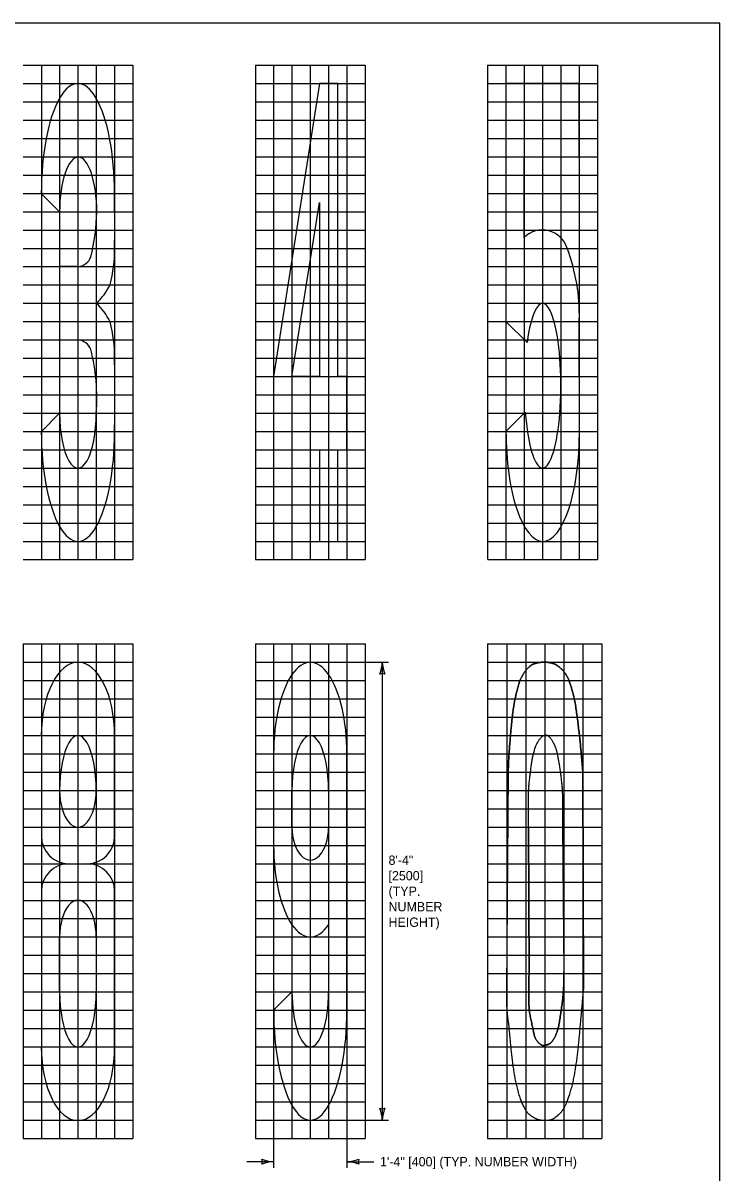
# Model space of a CAD drawing. Extents: x 49991.4 to 50021, y 49987.6 to 50011.4.
# Drawn here: x 50004.12 to 50008.61, y 50003.84 to 50011.26 of the extents above; entities that cross this region are included whole.
import ezdxf

# ---------------------------------------------------------------- set-up
doc = ezdxf.new("R2010")
doc.units = 0
for name, color, linetype in [('Level 1', 7, 'Continuous'), ('Level 2', 7, 'Continuous'), ('Level 3', 7, 'Continuous'), ('Level 9', 7, 'Continuous')]:
    doc.layers.add(name, color=color, linetype=linetype)

msp = doc.modelspace()

# ---------------------------------------------------------------- linework, layer by layer
at = {"layer": 'Level 1'}
for p, q in [((50007.7072, 50010.8724), (50007.2348, 50010.8724)), ((50007.2348, 50010.8724), (50007.2348, 50009.3367)), ((50007.7072, 50010.3999), (50007.7072, 50010.8724)), ((50007.3529, 50009.8798), (50007.3529, 50010.3999)), ((50007.3529, 50010.3999), (50007.7072, 50010.3999)), ((50004.2385, 50010.1636), (50004.3566, 50010.0456)), ((50004.7123, 50009.9274), (50004.711, 50010.1636)), ((50005.8549, 50008.9824), (50006.0321, 50010.1046)), ((50006.0321, 50010.1046), (50006.0321, 50008.9824)), ((50004.4751, 50009.6911), (50004.357, 50009.6911)), ((50004.357, 50009.6911), (50004.357, 50009.4549)), ((50004.357, 50009.4549), (50004.357, 50009.2186)), ((50007.2348, 50009.3367), (50007.3703, 50009.2012)), ((50007.7086, 50008.628), (50007.7074, 50009.3472)), ((50004.357, 50009.2186), (50004.4751, 50009.2186)), ((50005.7368, 50008.9824), (50005.7368, 50008.5099)), ((50006.0321, 50008.9824), (50005.8549, 50008.9824)), ((50006.2093, 50008.9824), (50006.1502, 50008.9824)), ((50006.2093, 50008.5099), (50006.2093, 50008.9824)), ((50004.357, 50008.7461), (50004.2389, 50008.628)), ((50007.3592, 50008.7524), (50007.2348, 50008.628)), ((50005.7368, 50008.5099), (50006.0321, 50008.5099)), ((50006.0321, 50008.5099), (50006.0321, 50007.9192)), ((50006.1502, 50007.9192), (50006.1502, 50008.5099)), ((50006.1502, 50008.5099), (50006.2093, 50008.5099)), ((50006.0321, 50007.9192), (50006.1502, 50007.9192)), ((50004.2389, 50006.6667), (50004.2389, 50006.0761)), ((50004.7114, 50006.0761), (50004.7114, 50006.6667)), ((50005.7368, 50006.5486), (50005.7368, 50005.958)), ((50006.2093, 50004.8948), (50006.2093, 50006.5486)), ((50005.855, 50006.0761), (50005.855, 50006.3123)), ((50006.0912, 50006.3123), (50006.0912, 50006.0761)), ((50004.2389, 50006.0761), (50004.2389, 50006.017)), ((50004.7114, 50006.017), (50004.7114, 50006.0761)), ((50004.2389, 50005.6626), (50004.2389, 50004.6586)), ((50004.7114, 50004.6586), (50004.7114, 50005.6626)), ((50006.0912, 50005.4465), (50006.0912, 50005.013)), ((50004.357, 50005.013), (50004.357, 50005.3673)), ((50004.5932, 50005.3673), (50004.5932, 50005.013)), ((50005.855, 50005.013), (50005.7368, 50004.8948))]:
    msp.add_line(p, q, dxfattribs=at)
msp.add_lwpolyline([(50008.6146, 50011.2628), (50000.3356, 50011.2628), (50000.3356, 50000.0624), (50008.6146, 50000.0624)], close=True, dxfattribs=at)
for points in [[(50006.1502, 50008.9824), (50006.1502, 50010.8724), (50006.0321, 50010.8724), (50005.7368, 50008.9824)], [(50007.2494, 50006.4264), (50007.2371, 50005.0264)], [(50007.7346, 50005.0284), (50007.7305, 50006.4303)], [(50007.3834, 50005.1428), (50007.3807, 50006.078)], [(50007.5988, 50006.0793), (50007.6082, 50005.1428)]]:
    msp.add_lwpolyline(points, dxfattribs=at)
for centre, radius, start, end in [((50007.4695, 50009.7605), 0.1669, 17.22202, 134.34836), ((50006.4978, 50009.38), 1.21, 358.44818, 20.8119)]:
    msp.add_arc(centre, radius, start, end, dxfattribs=at)
for centre, major_axis, ratio, start_param, end_param in [((50004.4748, 50010.1636), (0, 0.7087), 0.333309, 4.712389, 7.853982), ((50004.4766, 50010.0434), (0, -0.3544), 0.338649, 1.570796, 4.706242), ((50003.3124, 50010.0665), (0, 1.2845), 0.999928, 4.466044, 4.696062), ((49982.9544, 50010.0455), (0, 21.7597), 0.999928, 4.701532, 4.70696), ((50003.8487, 50009.7981), (0, 0.8627), 0.999928, 4.450566, 4.725288), ((50004.4655, 50009.7904), (0, 0.0998), 0.999928, 3.237525, 4.330136), ((50004.3421, 50009.7336), (0, 0.3751), 0.999928, 3.874855, 4.275301), ((50004.3421, 50009.1761), (0, 0.3751), 0.999928, 5.149477, 5.549923), ((50007.471, 50008.9233), (0, 0.5315), 0.222211, 5.501988, 7.303894), ((50003.8487, 50009.1116), (0, 0.8627), 0.999928, 4.69949, 4.974212), ((50007.471, 50008.9233), (0, 0.5315), 0.222211, 1.898175, 5.501988), ((50004.4655, 50009.1193), (0, 0.0998), 0.999928, 5.094642, 6.187253), ((50003.3124, 50008.8433), (0, 1.2845), 0.999928, 4.636675, 4.958734), ((49982.9544, 50008.8642), (0, 21.7597), 0.999928, 4.701532, 4.723246), ((50004.4751, 50008.7461), (0, 0.3544), 0.333302, 1.570796, 4.712389), ((50004.4751, 50008.628), (0, 0.7087), 0.333309, 1.570796, 4.712389), ((50007.4717, 50008.628), (0, 0.7088), 0.334262, 1.570796, 3.141593), ((50007.4717, 50008.628), (0, 0.7088), 0.334262, 3.141593, 4.712389), ((50004.4751, 50006.6667), (0, 0.4725), 0.499964, 0, 1.570796), ((50004.4751, 50006.6667), (0, 0.4725), 0.499964, 4.712389, 6.283185), ((50005.9731, 50006.5486), (0, -0.5906), 0.399971, 1.570796, 4.712389), ((50004.4751, 50006.3123), (0, 0.3544), 0.333309, 4.712389, 7.853982), ((50005.9731, 50006.3123), (0, -0.3544), 0.333309, 1.570796, 4.712389), ((50004.4751, 50006.3123), (0, 0.2363), 0.499964, 1.570796, 4.712389), ((50005.9731, 50006.0761), (0, -0.2125), 0.555853, 4.712389, 7.853982), ((50004.4161, 50006.017), (0, -0.1772), 0.999928, 4.712389, 6.283185), ((50004.5342, 50006.017), (0, -0.1772), 0.999928, 0, 1.570796), ((50005.9731, 50005.958), (0, 0.5906), 0.399971, 1.570796, 3.665191), ((50004.4161, 50005.6626), (0, -0.1772), 0.999928, 3.141593, 4.712389), ((50004.5342, 50005.6626), (0, 0.1772), 0.999928, 4.712389, 6.283185), ((50004.4751, 50005.3673), (0, 0.2363), 0.499964, 4.712389, 7.853982), ((50004.4751, 50005.013), (0, 0.3544), 0.333309, 1.570796, 4.712389), ((50005.9731, 50005.013), (0, -0.3544), 0.333309, 4.712389, 7.8539), ((50005.9731, 50004.8948), (0, 0.7087), 0.333309, 1.570796, 4.712389), ((50004.4751, 50004.6586), (0, 0.4761), 0.496158, 1.570834, 4.712389)]:
    msp.add_ellipse(centre, major_axis=major_axis, ratio=ratio, start_param=start_param, end_param=end_param, dxfattribs=at)
for points in [[(50007.7305, 50006.4303), (50007.7208, 50006.544), (50007.7095, 50006.6607), (50007.6952, 50006.7783), (50007.6787, 50006.897), (50007.6459, 50007.0126), (50007.6274, 50007.0522), (50007.6058, 50007.0838), (50007.575, 50007.1115), (50007.5462, 50007.1313), (50007.4805, 50007.1432), (50007.4158, 50007.1313), (50007.3911, 50007.1165), (50007.3665, 50007.0927), (50007.3429, 50007.0581), (50007.3223, 50007.0176), (50007.2905, 50006.899), (50007.2741, 50006.7803), (50007.2628, 50006.6587), (50007.2494, 50006.4827), (50007.2494, 50006.4264)], [(50007.3807, 50006.078), (50007.3793, 50006.1978), (50007.3793, 50006.3151), (50007.3927, 50006.4336), (50007.4074, 50006.5443), (50007.4436, 50006.641), (50007.4971, 50006.6835), (50007.5466, 50006.6139), (50007.5667, 50006.5482), (50007.5841, 50006.4374), (50007.5988, 50006.3163), (50007.5988, 50006.1953), (50007.5988, 50006.0793)], [(50007.6082, 50005.1428), (50007.6082, 50005.0243), (50007.5921, 50004.902), (50007.5747, 50004.786), (50007.5546, 50004.7281), (50007.5239, 50004.6791), (50007.4824, 50004.6662), (50007.465, 50004.6662), (50007.4235, 50004.7049), (50007.4048, 50004.7886), (50007.382, 50004.902), (50007.382, 50005.0205), (50007.3834, 50005.1428)], [(50007.2371, 50005.0264), (50007.2371, 50004.9048), (50007.2535, 50004.7872), (50007.2638, 50004.6665), (50007.2761, 50004.5519), (50007.2956, 50004.4302), (50007.3275, 50004.3136), (50007.3644, 50004.2424), (50007.3932, 50004.2147), (50007.4446, 50004.1851), (50007.5226, 50004.1851), (50007.5514, 50004.2019), (50007.5863, 50004.2315), (50007.6109, 50004.2651), (50007.6346, 50004.3146), (50007.6685, 50004.4302), (50007.689, 50004.5499), (50007.7034, 50004.6685), (50007.7136, 50004.7862), (50007.7249, 50004.9068), (50007.7346, 50005.0284)]]:
    msp.add_open_spline(points, degree=2, dxfattribs=at)
at = {"layer": 'Level 3'}
for p, q in [((50006.0731, 50007.1392), (50006.4774, 50007.1392)), ((50006.4374, 50007.1392), (50006.4374, 50004.1861)), ((50005.7368, 50004.6586), (50005.7368, 50003.8779)), ((50006.2093, 50004.6586), (50006.2093, 50003.8779)), ((50006.0731, 50004.1861), (50006.1693, 50004.1861)), ((50006.2493, 50004.1861), (50006.4774, 50004.1861)), ((50005.7368, 50003.9179), (50005.5634, 50003.9179)), ((50006.2093, 50003.9179), (50006.3827, 50003.9179))]:
    msp.add_line(p, q, dxfattribs=at)
for centre, radius, start, end in [((50006.2153, 50007.1484), 0.2223, 337.45601, 357.63952), ((50006.6701, 50007.1507), 0.233, 182.82731, 202.07716), ((50006.4374, 50007.011), 0.0548, 72.13882, 107.86118), ((50006.4374, 50004.3143), 0.0548, 252.13882, 287.86118), ((50006.2047, 50004.1746), 0.233, 2.82731, 22.07716), ((50006.6596, 50004.1769), 0.2223, 157.45601, 177.63952), ((50005.746, 50004.1401), 0.2223, 247.45601, 267.63952), ((50005.6086, 50003.9179), 0.0548, 342.13882, 17.86118), ((50005.7483, 50003.6852), 0.233, 92.82731, 112.07716), ((50006.1978, 50004.1507), 0.233, 272.82731, 292.07716), ((50006.2001, 50003.6958), 0.2223, 67.45601, 87.63952), ((50006.3375, 50003.9179), 0.0548, 162.13882, 197.86118)]:
    msp.add_arc(centre, radius, start, end, dxfattribs=at)
at = {"layer": 'Level 9'}
for p, q in [((50008.6146, 50011.2628), (50008.6146, 50011.2628)), ((50004.1207, 50010.9905), (50004.8294, 50010.9905)), ((50004.2389, 50010.9905), (50004.2389, 50007.8011)), ((50004.357, 50010.9905), (50004.357, 50007.8011)), ((50004.4751, 50010.9905), (50004.4751, 50007.8011)), ((50004.5932, 50010.9905), (50004.5932, 50007.8011)), ((50004.7113, 50010.9905), (50004.7113, 50007.8011)), ((50004.8294, 50010.9905), (50004.8294, 50007.8011)), ((50005.6187, 50010.9905), (50006.3274, 50010.9905)), ((50005.6187, 50010.9905), (50005.6187, 50007.8011)), ((50005.7368, 50010.9905), (50005.7368, 50007.8011)), ((50005.8549, 50010.9905), (50005.8549, 50007.8011)), ((50005.973, 50010.9905), (50005.973, 50007.8011)), ((50006.0912, 50010.9905), (50006.0912, 50007.8011)), ((50006.2093, 50010.9905), (50006.2093, 50007.8011)), ((50006.3274, 50010.9905), (50006.3274, 50007.8011)), ((50007.1166, 50010.9905), (50007.8253, 50010.9905)), ((50007.1166, 50010.9905), (50007.1166, 50007.8011)), ((50007.2348, 50010.9905), (50007.2348, 50007.8011)), ((50007.3529, 50010.9905), (50007.3529, 50007.8011)), ((50007.471, 50010.9905), (50007.471, 50007.8011)), ((50007.5891, 50010.9905), (50007.5891, 50007.8011)), ((50007.7072, 50010.9905), (50007.7072, 50007.8011)), ((50007.8253, 50010.9905), (50007.8253, 50007.8011)), ((50004.1208, 50010.8724), (50004.8295, 50010.8724)), ((50005.6187, 50010.8724), (50006.3275, 50010.8724)), ((50006.1502, 50010.8724), (50006.0321, 50010.8724)), ((50007.1167, 50010.8724), (50007.8253, 50010.8724)), ((50004.1208, 50010.7542), (50004.8295, 50010.7542)), ((50005.6187, 50010.7542), (50006.3275, 50010.7542)), ((50007.1167, 50010.7542), (50007.8253, 50010.7542)), ((50004.1208, 50010.6361), (50004.8295, 50010.6361)), ((50005.6187, 50010.6361), (50006.3275, 50010.6361)), ((50007.1167, 50010.6361), (50007.8253, 50010.6361)), ((50004.1208, 50010.518), (50004.8295, 50010.518)), ((50005.6187, 50010.518), (50006.3275, 50010.518)), ((50007.1167, 50010.518), (50007.8253, 50010.518)), ((50004.1208, 50010.3999), (50004.8295, 50010.3999)), ((50005.6187, 50010.3999), (50006.3275, 50010.3999)), ((50007.1167, 50010.3999), (50007.8253, 50010.3999)), ((50004.1208, 50010.2817), (50004.8295, 50010.2817)), ((50005.6187, 50010.2817), (50006.3275, 50010.2817)), ((50007.1167, 50010.2817), (50007.8253, 50010.2817)), ((50004.1208, 50010.1636), (50004.8295, 50010.1636)), ((50005.6187, 50010.1636), (50006.3275, 50010.1636)), ((50007.1167, 50010.1636), (50007.8253, 50010.1636)), ((50004.1208, 50010.0455), (50004.8295, 50010.0455)), ((50005.6187, 50010.0455), (50006.3275, 50010.0455)), ((50007.1167, 50010.0455), (50007.8253, 50010.0455)), ((50004.1208, 50009.9274), (50004.8295, 50009.9274)), ((50005.6187, 50009.9274), (50006.3275, 50009.9274)), ((50007.1167, 50009.9274), (50007.8253, 50009.9274)), ((50004.1208, 50009.8092), (50004.8295, 50009.8092)), ((50005.6187, 50009.8092), (50006.3275, 50009.8092)), ((50007.1167, 50009.8092), (50007.8253, 50009.8092)), ((50004.1208, 50009.6911), (50004.8295, 50009.6911)), ((50005.6187, 50009.6911), (50006.3275, 50009.6911)), ((50007.1167, 50009.6911), (50007.8253, 50009.6911)), ((50004.1208, 50009.573), (50004.8295, 50009.573)), ((50005.6187, 50009.573), (50006.3275, 50009.573)), ((50007.1167, 50009.573), (50007.8253, 50009.573)), ((50004.1208, 50009.4549), (50004.8295, 50009.4549)), ((50004.5932, 50009.4549), (50004.5932, 50009.4549)), ((50005.6187, 50009.4549), (50006.3275, 50009.4549)), ((50007.1167, 50009.4549), (50007.8253, 50009.4549)), ((50004.1208, 50009.3367), (50004.8295, 50009.3367)), ((50005.6187, 50009.3367), (50006.3275, 50009.3367)), ((50007.1167, 50009.3367), (50007.8253, 50009.3367)), ((50004.1208, 50009.2186), (50004.8295, 50009.2186)), ((50004.357, 50009.2186), (50004.357, 50009.2186)), ((50005.6187, 50009.2186), (50006.3275, 50009.2186)), ((50007.1167, 50009.2186), (50007.8253, 50009.2186)), ((50004.1208, 50009.1005), (50004.8295, 50009.1005)), ((50005.6187, 50009.1005), (50006.3275, 50009.1005)), ((50007.1167, 50009.1005), (50007.8253, 50009.1005)), ((50004.1208, 50008.9824), (50004.8295, 50008.9824)), ((50005.6187, 50008.9824), (50006.3275, 50008.9824)), ((50007.1167, 50008.9824), (50007.8253, 50008.9824)), ((50004.1208, 50008.8642), (50004.8295, 50008.8642)), ((50005.6187, 50008.8642), (50006.3275, 50008.8642)), ((50007.1167, 50008.8642), (50007.8253, 50008.8642)), ((50004.1208, 50008.7461), (50004.8295, 50008.7461)), ((50004.357, 50008.7461), (50004.357, 50008.7461)), ((50004.5932, 50008.7461), (50004.5932, 50008.7461)), ((50005.6187, 50008.7461), (50006.3275, 50008.7461)), ((50007.1167, 50008.7461), (50007.8253, 50008.7461)), ((50004.1208, 50008.628), (50004.8295, 50008.628)), ((50005.6187, 50008.628), (50006.3275, 50008.628)), ((50007.1167, 50008.628), (50007.8253, 50008.628)), ((50004.1208, 50008.5099), (50004.8295, 50008.5099)), ((50005.6187, 50008.5099), (50006.3275, 50008.5099)), ((50007.1167, 50008.5099), (50007.8253, 50008.5099)), ((50004.1208, 50008.3917), (50004.8295, 50008.3917)), ((50005.6187, 50008.3917), (50006.3275, 50008.3917)), ((50007.1167, 50008.3917), (50007.8253, 50008.3917)), ((50004.1208, 50008.2736), (50004.8295, 50008.2736)), ((50005.6187, 50008.2736), (50006.3275, 50008.2736)), ((50007.1167, 50008.2736), (50007.8253, 50008.2736)), ((50004.1208, 50008.1555), (50004.8295, 50008.1555)), ((50005.6187, 50008.1555), (50006.3275, 50008.1555)), ((50007.1167, 50008.1555), (50007.8253, 50008.1555)), ((50004.1208, 50008.0374), (50004.8295, 50008.0374)), ((50005.6187, 50008.0374), (50006.3275, 50008.0374)), ((50007.1167, 50008.0374), (50007.8253, 50008.0374)), ((50004.1208, 50007.9192), (50004.8295, 50007.9192)), ((50005.6187, 50007.9192), (50006.3275, 50007.9192)), ((50007.1167, 50007.9192), (50007.8253, 50007.9192)), ((50004.1208, 50007.8011), (50004.8295, 50007.8011)), ((50005.6187, 50007.8011), (50006.3275, 50007.8011)), ((50007.1167, 50007.8011), (50007.8253, 50007.8011)), ((50004.1208, 50007.2573), (50004.1208, 50004.0679)), ((50004.1208, 50007.2573), (50004.8295, 50007.2573)), ((50004.2389, 50007.2573), (50004.2389, 50004.0679)), ((50004.357, 50007.2573), (50004.357, 50004.0679)), ((50004.4751, 50007.2573), (50004.4751, 50004.0679)), ((50004.5932, 50007.2573), (50004.5932, 50004.0679)), ((50004.7114, 50007.2573), (50004.7114, 50004.0679)), ((50004.8295, 50007.2573), (50004.8295, 50004.0679)), ((50005.6187, 50007.2573), (50005.6187, 50004.0679)), ((50005.6187, 50007.2573), (50006.3274, 50007.2573)), ((50005.7368, 50007.2573), (50005.7368, 50004.0679)), ((50005.855, 50007.2573), (50005.855, 50004.0679)), ((50005.9731, 50007.2573), (50005.9731, 50004.0679)), ((50006.0912, 50007.2573), (50006.0912, 50004.0679)), ((50006.2093, 50007.2573), (50006.2093, 50004.0679)), ((50006.3274, 50007.2573), (50006.3274, 50004.0679)), ((50007.1166, 50007.2573), (50007.1166, 50004.0679)), ((50007.1166, 50007.2573), (50007.8529, 50007.2573)), ((50007.2394, 50007.2573), (50007.2394, 50004.0679)), ((50007.3621, 50007.2573), (50007.3621, 50004.0679)), ((50007.4848, 50007.2573), (50007.4848, 50004.0679)), ((50007.6075, 50007.2573), (50007.6075, 50004.0679)), ((50007.7302, 50007.2573), (50007.7302, 50004.0679)), ((50007.8529, 50007.2573), (50007.8529, 50004.0679)), ((50004.1208, 50007.1392), (50004.8295, 50007.1392)), ((50005.6187, 50007.1392), (50006.3274, 50007.1392)), ((50007.1166, 50007.1392), (50007.8529, 50007.1392)), ((50004.1208, 50007.0211), (50004.8295, 50007.0211)), ((50005.6187, 50007.0211), (50006.3274, 50007.0211)), ((50007.1166, 50007.0211), (50007.8529, 50007.0211)), ((50004.1208, 50006.903), (50004.8295, 50006.903)), ((50005.6187, 50006.903), (50006.3274, 50006.903)), ((50007.1166, 50006.9029), (50007.8529, 50006.9029)), ((50004.1208, 50006.7848), (50004.8295, 50006.7848)), ((50005.6187, 50006.7848), (50006.3274, 50006.7848)), ((50007.1166, 50006.7848), (50007.8529, 50006.7848)), ((50004.1208, 50006.6667), (50004.8295, 50006.6667)), ((50005.6187, 50006.6667), (50006.3274, 50006.6667)), ((50007.1166, 50006.6667), (50007.8529, 50006.6667)), ((50004.1208, 50006.5486), (50004.8295, 50006.5486)), ((50005.6187, 50006.5486), (50006.3274, 50006.5486)), ((50007.1166, 50006.5486), (50007.8529, 50006.5486)), ((50004.1208, 50006.4305), (50004.8295, 50006.4305)), ((50005.6187, 50006.4305), (50006.3274, 50006.4305)), ((50007.1166, 50006.4304), (50007.8529, 50006.4304)), ((50007.2494, 50006.4264), (50007.2371, 50005.0264)), ((50007.7305, 50006.4303), (50007.7346, 50005.0284)), ((50004.1208, 50006.3123), (50004.8295, 50006.3123)), ((50005.6187, 50006.3123), (50006.3274, 50006.3123)), ((50007.1166, 50006.3123), (50007.8529, 50006.3123)), ((50004.1208, 50006.1942), (50004.8295, 50006.1942)), ((50005.6187, 50006.1942), (50006.3274, 50006.1942)), ((50007.1166, 50006.1942), (50007.8529, 50006.1942)), ((50004.1208, 50006.0761), (50004.8295, 50006.0761)), ((50005.6187, 50006.0761), (50006.3274, 50006.0761)), ((50007.1166, 50006.0761), (50007.8529, 50006.0761)), ((50007.3807, 50006.078), (50007.3834, 50005.1428)), ((50007.5988, 50006.0793), (50007.6082, 50005.1428)), ((50004.1208, 50005.958), (50004.8295, 50005.958)), ((50005.6187, 50005.958), (50006.3274, 50005.958)), ((50007.1166, 50005.9579), (50007.8529, 50005.9579)), ((50004.1208, 50005.8398), (50004.8295, 50005.8398)), ((50004.5017, 50005.8124), (50004.5017, 50005.8124)), ((50005.6187, 50005.8398), (50006.3274, 50005.8398)), ((50007.1166, 50005.8398), (50007.8529, 50005.8398)), ((50004.1208, 50005.7217), (50004.8295, 50005.7217)), ((50005.6187, 50005.7217), (50006.3274, 50005.7217)), ((50007.1166, 50005.7217), (50007.8529, 50005.7217)), ((50004.1208, 50005.6036), (50004.8295, 50005.6036)), ((50005.6187, 50005.6036), (50006.3274, 50005.6036)), ((50007.1166, 50005.6036), (50007.8529, 50005.6036)), ((50004.1208, 50005.4855), (50004.8295, 50005.4855)), ((50005.6187, 50005.4855), (50006.3274, 50005.4855)), ((50007.1166, 50005.4854), (50007.8529, 50005.4854)), ((50004.1208, 50005.3673), (50004.8295, 50005.3673)), ((50005.6187, 50005.3673), (50006.3274, 50005.3673)), ((50007.1166, 50005.3673), (50007.8529, 50005.3673)), ((50004.1208, 50005.2492), (50004.8295, 50005.2492)), ((50005.6187, 50005.2492), (50006.3274, 50005.2492)), ((50007.1166, 50005.2492), (50007.8529, 50005.2492)), ((50004.1208, 50005.1311), (50004.8295, 50005.1311)), ((50005.6187, 50005.1311), (50006.3274, 50005.1311)), ((50007.1166, 50005.1311), (50007.8529, 50005.1311)), ((50004.1208, 50005.013), (50004.8295, 50005.013)), ((50005.6187, 50005.013), (50006.3274, 50005.013)), ((50007.1166, 50005.0129), (50007.8529, 50005.0129)), ((50004.1208, 50004.8948), (50004.8295, 50004.8948)), ((50005.6187, 50004.8948), (50006.3274, 50004.8948)), ((50007.1166, 50004.8948), (50007.8529, 50004.8948)), ((50004.1208, 50004.7767), (50004.8295, 50004.7767)), ((50005.6187, 50004.7767), (50006.3274, 50004.7767)), ((50007.1166, 50004.7767), (50007.8529, 50004.7767)), ((50004.1208, 50004.6586), (50004.8295, 50004.6586)), ((50005.6187, 50004.6586), (50006.3274, 50004.6586)), ((50007.1166, 50004.6586), (50007.8529, 50004.6586)), ((50004.1208, 50004.5405), (50004.8295, 50004.5405)), ((50005.6187, 50004.5405), (50006.3274, 50004.5405)), ((50007.1166, 50004.5404), (50007.8529, 50004.5404)), ((50004.1208, 50004.4223), (50004.8295, 50004.4223)), ((50005.6187, 50004.4223), (50006.3274, 50004.4223)), ((50007.1166, 50004.4223), (50007.8529, 50004.4223)), ((50004.1208, 50004.3042), (50004.8295, 50004.3042)), ((50005.6187, 50004.3042), (50006.3274, 50004.3042)), ((50007.1166, 50004.3042), (50007.8529, 50004.3042)), ((50004.1208, 50004.1861), (50004.8295, 50004.1861)), ((50005.6187, 50004.1861), (50006.3274, 50004.1861)), ((50007.1166, 50004.1861), (50007.8529, 50004.1861)), ((50004.1208, 50004.0679), (50004.8295, 50004.0679)), ((50005.6187, 50004.0679), (50006.3274, 50004.0679)), ((50007.1166, 50004.0679), (50007.8529, 50004.0679))]:
    msp.add_line(p, q, dxfattribs=at)
for points in [[(50007.2494, 50006.4264), (50007.2494, 50006.4827), (50007.2628, 50006.6587), (50007.2741, 50006.7803), (50007.2905, 50006.899), (50007.3223, 50007.0176), (50007.3429, 50007.0581), (50007.3665, 50007.0927), (50007.3911, 50007.1165), (50007.4158, 50007.1313), (50007.4805, 50007.1432), (50007.5462, 50007.1313), (50007.575, 50007.1115), (50007.6058, 50007.0838), (50007.6274, 50007.0522), (50007.6459, 50007.0126), (50007.6787, 50006.897), (50007.6952, 50006.7783), (50007.7095, 50006.6607), (50007.7208, 50006.544), (50007.7305, 50006.4303)], [(50007.3807, 50006.078), (50007.3793, 50006.1978), (50007.3793, 50006.3151), (50007.3927, 50006.4336), (50007.4074, 50006.5443), (50007.4436, 50006.641), (50007.4971, 50006.6835), (50007.5466, 50006.6139), (50007.5667, 50006.5482), (50007.5841, 50006.4374), (50007.5988, 50006.3163), (50007.5988, 50006.1953), (50007.5988, 50006.0793)], [(50007.3834, 50005.1428), (50007.382, 50005.0205), (50007.382, 50004.902), (50007.4048, 50004.7886), (50007.4235, 50004.7049), (50007.465, 50004.6662), (50007.4824, 50004.6662), (50007.5239, 50004.6791), (50007.5546, 50004.7281), (50007.5747, 50004.786), (50007.5921, 50004.902), (50007.6082, 50005.0243), (50007.6082, 50005.1428)], [(50007.2371, 50005.0264), (50007.2371, 50004.9048), (50007.2535, 50004.7872), (50007.2638, 50004.6665), (50007.2761, 50004.5519), (50007.2956, 50004.4302), (50007.3275, 50004.3136), (50007.3644, 50004.2424), (50007.3932, 50004.2147), (50007.4446, 50004.1851), (50007.5226, 50004.1851), (50007.5514, 50004.2019), (50007.5863, 50004.2315), (50007.6109, 50004.2651), (50007.6346, 50004.3146), (50007.6685, 50004.4302), (50007.689, 50004.5499), (50007.7034, 50004.6685), (50007.7136, 50004.7862), (50007.7249, 50004.9068), (50007.7346, 50005.0284)]]:
    msp.add_open_spline(points, degree=2, dxfattribs=at)

# ---------------------------------------------------------------- texts
at = {"layer": 'Level 2'}
for s, p in [('8\'-4"', (50006.4774, 50005.8326)), ('[2500]', (50006.4774, 50005.7326)), ('(TYP.', (50006.4774, 50005.6326)), ('NUMBER', (50006.4774, 50005.5326)), ('HEIGHT)', (50006.4774, 50005.4326)), ('1\'-4" [400] (TYP. NUMBER WIDTH)', (50006.4227, 50003.8879))]:
    msp.add_text(s, height=0.06, dxfattribs=at).set_placement(p)

doc.saveas('drawing.dxf')
